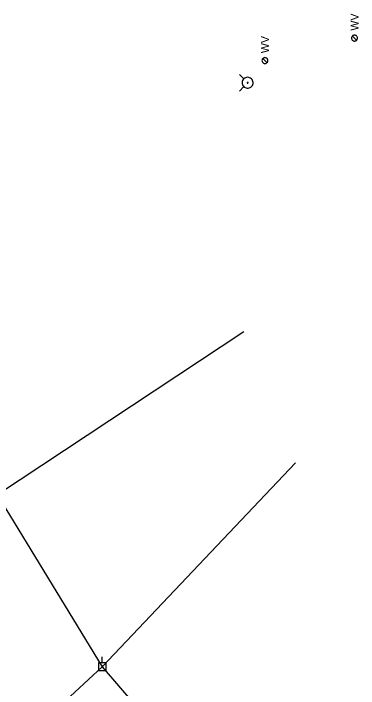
# Model space of a CAD drawing. Extents: x 596028 to 606371, y 330010 to 403088.
# Drawn here: x 605146.6 to 605312.6, y 335514.8 to 335839.2 of the extents above; entities that cross this region are included whole.
import ezdxf

# ---------------------------------------------------------------- set-up
doc = ezdxf.new("R2010")
doc.units = 0
for name, color, linetype in [('E_UTL_E_UG', 7, 'Continuous'), ('E_UTL_EPowerPole', 7, 'Continuous'), ('E_UTL_Overhead', 7, 'Continuous'), ('E_UTL_W', 7, 'Continuous'), ('E_UTL_WHydrant', 7, 'Continuous')]:
    doc.layers.add(name, color=color, linetype=linetype)

msp = doc.modelspace()

# ---------------------------------------------------------------- linework, layer by layer
at = {"layer": 'E_UTL_E_UG'}
msp.add_line((605093.66, 335437.17), (605189.35, 335525.28), dxfattribs=at)
at = {"layer": 'E_UTL_EPowerPole'}
for points in [[(605189.31, 335527.13), (605189.31, 335530.04)], [(605191.16, 335527.13), (605187.47, 335527.13)], [(605187.47, 335527.13), (605187.47, 335523.44)], [(605191.16, 335523.44), (605191.16, 335527.13)], [(605187.47, 335523.44), (605191.16, 335523.44)], [(605189.58, 335525.28), (605189.58, 335525.33), (605189.57, 335525.37), (605189.55, 335525.41), (605189.52, 335525.45), (605189.48, 335525.48), (605189.45, 335525.5), (605189.4, 335525.52), (605189.36, 335525.52), (605189.31, 335525.52), (605189.27, 335525.51), (605189.23, 335525.49), (605189.19, 335525.46), (605189.16, 335525.43), (605189.13, 335525.39), (605189.12, 335525.35), (605189.11, 335525.31), (605189.11, 335525.26), (605189.12, 335525.22), (605189.13, 335525.17), (605189.16, 335525.14), (605189.19, 335525.1), (605189.23, 335525.08), (605189.27, 335525.06), (605189.31, 335525.05), (605189.36, 335525.05), (605189.4, 335525.05), (605189.45, 335525.07), (605189.48, 335525.09), (605189.52, 335525.12), (605189.55, 335525.16), (605189.57, 335525.2), (605189.58, 335525.24), (605189.58, 335525.28)]]:
    msp.add_lwpolyline(points, dxfattribs=at)
at = {"layer": 'E_UTL_Overhead'}
for p, q in [((605138.78, 335607.99), (605257.45, 335686.37)), ((605189.35, 335525.28), (605282.31, 335623.21)), ((605138.75, 335607.93), (605189.35, 335525.28)), ((605189.35, 335525.28), (605263.14, 335438.82))]:
    msp.add_line(p, q, dxfattribs=at)
at = {"layer": 'E_UTL_W'}
for points in [[(605310.65, 335828.77), (605310.38, 335828.75), (605310.12, 335828.67), (605309.88, 335828.55), (605309.66, 335828.38), (605309.49, 335828.18), (605309.35, 335827.94), (605309.26, 335827.68), (605309.22, 335827.42), (605309.24, 335827.15), (605309.3, 335826.88), (605309.41, 335826.64), (605309.57, 335826.41), (605309.77, 335826.23), (605309.99, 335826.08), (605310.25, 335825.98), (605310.51, 335825.93), (605310.78, 335825.93), (605311.05, 335825.98), (605311.3, 335826.08), (605311.53, 335826.23), (605311.73, 335826.41), (605311.88, 335826.64), (605312, 335826.88), (605312.06, 335827.15), (605312.07, 335827.42), (605312.03, 335827.68), (605311.94, 335827.94), (605311.81, 335828.18), (605311.63, 335828.38), (605311.42, 335828.55), (605311.18, 335828.67), (605310.92, 335828.75), (605310.65, 335828.77)], [(605311.66, 335826.34), (605309.64, 335828.36)], [(605267.58, 335817.96), (605267.31, 335817.94), (605267.05, 335817.86), (605266.81, 335817.74), (605266.59, 335817.57), (605266.42, 335817.37), (605266.28, 335817.13), (605266.19, 335816.87), (605266.15, 335816.61), (605266.17, 335816.34), (605266.23, 335816.07), (605266.34, 335815.83), (605266.5, 335815.6), (605266.7, 335815.42), (605266.92, 335815.27), (605267.17, 335815.17), (605267.44, 335815.12), (605267.71, 335815.12), (605267.98, 335815.17), (605268.23, 335815.27), (605268.46, 335815.42), (605268.65, 335815.6), (605268.81, 335815.83), (605268.92, 335816.07), (605268.99, 335816.34), (605269, 335816.61), (605268.96, 335816.87), (605268.87, 335817.13), (605268.74, 335817.37), (605268.56, 335817.57), (605268.35, 335817.74), (605268.11, 335817.86), (605267.85, 335817.94), (605267.58, 335817.96)], [(605268.58, 335815.53), (605266.57, 335817.55)]]:
    msp.add_lwpolyline(points, dxfattribs=at)
at = {"layer": 'E_UTL_WHydrant'}
for points in [[(605257.4, 335807.74), (605255.26, 335809.88)], [(605259.24, 335808.53), (605258.74, 335808.48), (605258.27, 335808.34), (605257.82, 335808.11), (605257.43, 335807.8), (605257.1, 335807.42), (605256.85, 335806.99), (605256.69, 335806.52), (605256.62, 335806.03), (605256.64, 335805.53), (605256.76, 335805.05), (605256.97, 335804.59), (605257.26, 335804.19), (605257.62, 335803.84), (605258.04, 335803.57), (605258.5, 335803.39), (605258.99, 335803.29), (605259.49, 335803.29), (605259.98, 335803.39), (605260.44, 335803.57), (605260.86, 335803.84), (605261.22, 335804.19), (605261.51, 335804.59), (605261.72, 335805.05), (605261.84, 335805.53), (605261.86, 335806.03), (605261.79, 335806.52), (605261.63, 335806.99), (605261.38, 335807.42), (605261.05, 335807.8), (605260.66, 335808.11), (605260.21, 335808.34), (605259.74, 335808.48), (605259.24, 335808.53)], [(605259.24, 335806.1), (605259.2, 335806.1), (605259.17, 335806.09), (605259.13, 335806.07), (605259.1, 335806.05), (605259.08, 335806.02), (605259.06, 335805.99), (605259.05, 335805.95), (605259.04, 335805.91), (605259.04, 335805.87), (605259.05, 335805.84), (605259.07, 335805.8), (605259.09, 335805.77), (605259.12, 335805.75), (605259.15, 335805.72), (605259.18, 335805.71), (605259.22, 335805.7), (605259.26, 335805.7), (605259.3, 335805.71), (605259.33, 335805.72), (605259.36, 335805.75), (605259.39, 335805.77), (605259.41, 335805.8), (605259.43, 335805.84), (605259.44, 335805.87), (605259.44, 335805.91), (605259.43, 335805.95), (605259.42, 335805.99), (605259.4, 335806.02), (605259.38, 335806.05), (605259.35, 335806.07), (605259.31, 335806.09), (605259.28, 335806.1), (605259.24, 335806.1)], [(605257.4, 335804.07), (605255.26, 335801.93)]]:
    msp.add_lwpolyline(points, dxfattribs=at)

# ---------------------------------------------------------------- texts
at = {"layer": 'E_UTL_W'}
for p in [(605312.57, 335830.91), (605269.5, 335820.1)]:
    msp.add_text('WV', height=3.85, rotation=90, dxfattribs=at).set_placement(p)

doc.saveas('drawing.dxf')
